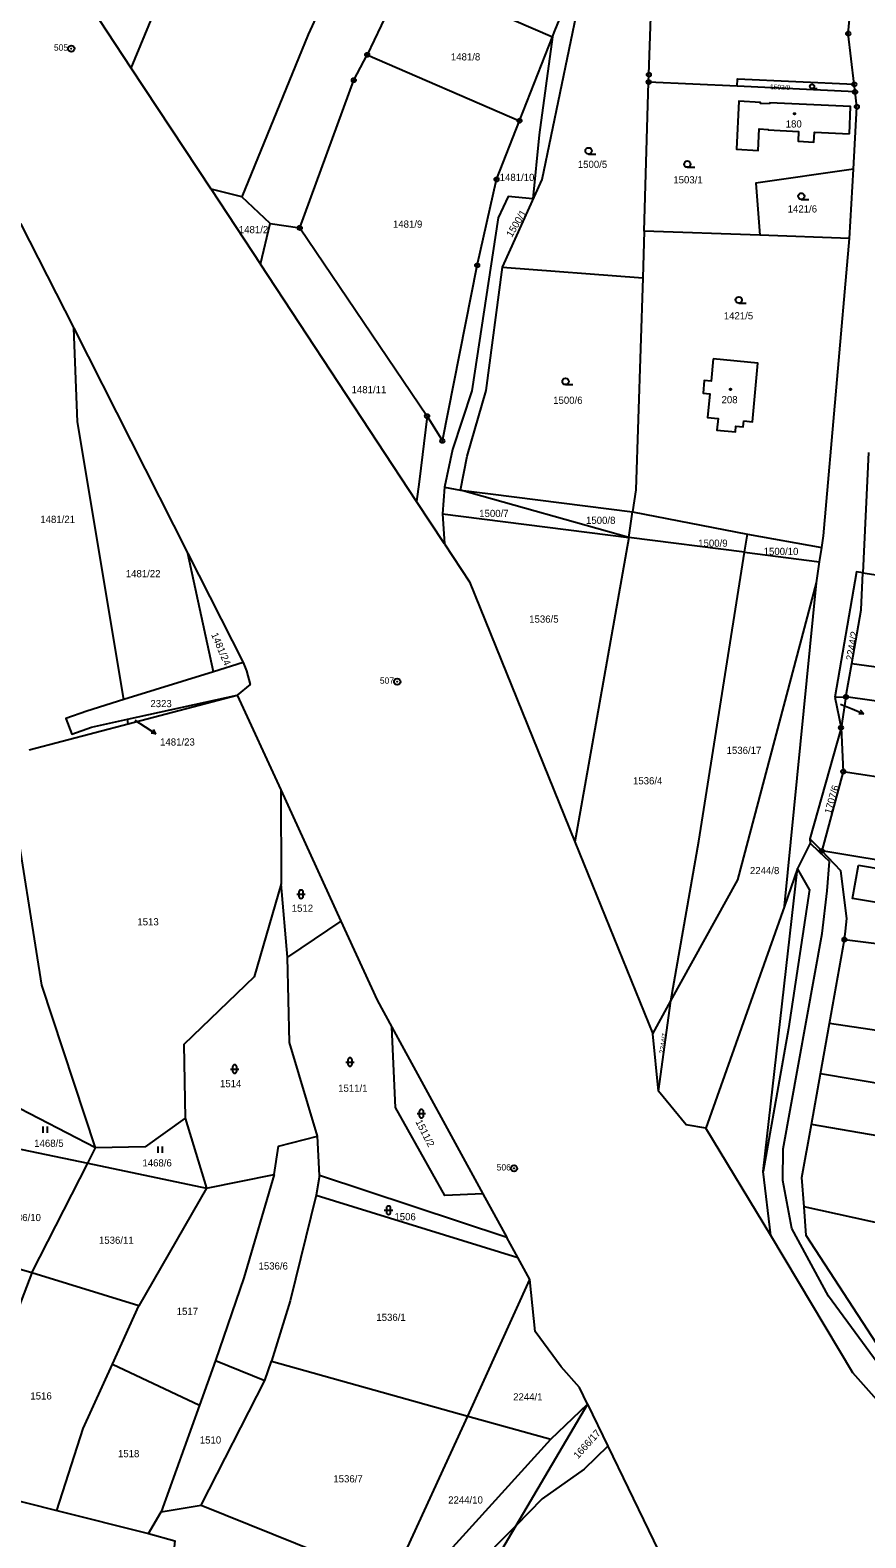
# Model space of a CAD drawing. Extents: x -725728 to -720881, y -1068679 to -1063504.
# Drawn here: x -723290.5 to -723092.7, y -1066402.9 to -1066046.1 of the extents above; entities that cross this region are included whole.
import ezdxf

# ---------------------------------------------------------------- set-up
doc = ezdxf.new("R2010")
doc.units = 0
for name, color, linetype in [('Hranice parcel', 7, 'Continuous'), ('Parcelní čísla', 7, 'Continuous'), ('Pop  PČ popisy', 7, 'Continuous'), ('Vnitřní kresba', 7, 'Continuous'), ('Značky bodu BP', 7, 'Continuous'), ('Značky budov', 7, 'Continuous'), ('Značky kultur', 7, 'Continuous')]:
    doc.layers.add(name, color=color, linetype=linetype)

# ---------------------------------------------------------------- blocks, each defined once
blk = doc.blocks.new('4.02_4')
at = {"layer": 'Značky budov'}
blk.add_circle((-0.001, 0), 0.0175, dxfattribs=at)
blk = doc.blocks.new('1029_117')
at = {"layer": 'Pop  PČ popisy'}
for p, q in [((0, 0), (0.276, -0.117)), ((0.276, -0.117), (0.164, -0.124)), ((0.276, -0.117), (0.204, -0.032))]:
    blk.add_line(p, q, dxfattribs=at)
blk = doc.blocks.new('1029_176')
at = {"layer": 'Pop  PČ popisy'}
for p, q in [((0, 0), (0.252, -0.163)), ((0.252, -0.163), (0.14, -0.151)), ((0.252, -0.163), (0.195, -0.067))]:
    blk.add_line(p, q, dxfattribs=at)
blk = doc.blocks.new('3.04_2')
at = {"layer": 'Značky kultur'}
blk.add_line((0.001, 0), (0.176, 0), dxfattribs=at)
blk.add_circle((0.001, 0.075), 0.075, dxfattribs=at)
blk = doc.blocks.new('3.16_3')
at = {"layer": 'Značky kultur'}
for p, q in [((-0.1, 0.1), (0.1, 0.1)), ((-0.05, 0.15), (-0.05, 0.05)), ((0.05, 0.05), (0.05, 0.15))]:
    blk.add_line(p, q, dxfattribs=at)
for centre, start, end in [((0, 0.15), 0, 180), ((0, 0.05), 180, 359.9879)]:
    blk.add_arc(centre, 0.05, start, end, dxfattribs=at)
blk = doc.blocks.new('3.16_2')
at = {"layer": 'Značky kultur'}
for p, q in [((-0.1, 0.1), (0.1, 0.1)), ((-0.05, 0.15), (-0.05, 0.05)), ((0.05, 0.05), (0.05, 0.15))]:
    blk.add_line(p, q, dxfattribs=at)
for centre, start, end in [((0, 0.15), 0, 180), ((0, 0.05), 180, 359.9879)]:
    blk.add_arc(centre, 0.05, start, end, dxfattribs=at)
blk = doc.blocks.new('3.04_4')
at = {"layer": 'Značky kultur'}
blk.add_line((0, 0), (0.118, 0), dxfattribs=at)
blk.add_circle((0, 0.05), 0.0502, dxfattribs=at)
blk = doc.blocks.new('3.06_1')
at = {"layer": 'Značky kultur'}
for p, q in [((-0.051, 0), (-0.051, 0.15)), ((0.049, 0), (0.049, 0.15))]:
    blk.add_line(p, q, dxfattribs=at)
blk = doc.blocks.new('1.01_1')
at = {"layer": 'Značky bodu BP'}
for radius in [0.075, 0.003]:
    blk.add_circle((0, 0), radius, dxfattribs=at)
blk = doc.blocks.new('1.05_1')
at = {"layer": 'Značky bodu BP'}
for radius in [0.05, 0.00303]:
    blk.add_circle((0, 0), radius, dxfattribs=at)
blk = doc.blocks.new('1.05_2')
at = {"layer": 'Značky bodu BP'}
for radius in [0.05, 0.00303]:
    blk.add_circle((0, 0), radius, dxfattribs=at)

msp = doc.modelspace()

# ---------------------------------------------------------------- linework, layer by layer
at = {"layer": 'Hranice parcel'}
for p, q in [((-723201.59, -1066032.7), (-723210.75, -1066051.97)), ((-723201.59, -1066032.7), (-723166.93, -1066047.71)), ((-723266.59, -1066055.14), (-723277.95, -1066037.89)), ((-723174.71, -1066067.58), (-723166.93, -1066047.71)), ((-723210.75, -1066051.97), (-723174.71, -1066067.58)), ((-723247.72, -1066083.8), (-723266.59, -1066055.14)), ((-723145.19, -1066093.7), (-723144.14, -1066058.44)), ((-723123.21, -1066059.43), (-723144.14, -1066058.44)), ((-723095.28, -1066060.75), (-723123.21, -1066059.43)), ((-723095.28, -1066060.75), (-723095.49, -1066058.96)), ((-723096.6, -1066095.41), (-723095.69, -1066079.02)), ((-723240.42, -1066085.57), (-723247.72, -1066083.8)), ((-723247.72, -1066083.8), (-723236.02, -1066101.56)), ((-723233.7, -1066091.89), (-723240.42, -1066085.57)), ((-723292.77, -1066091.87), (-723280.22, -1066116.65)), ((-723236.02, -1066101.56), (-723233.7, -1066091.89)), ((-723233.7, -1066091.89), (-723226.7, -1066092.94)), ((-723226.7, -1066092.94), (-723196.58, -1066137.49)), ((-723145.19, -1066093.7), (-723145.5, -1066104.76)), ((-723117.81, -1066094.66), (-723145.19, -1066093.7)), ((-723096.6, -1066095.41), (-723117.81, -1066094.66)), ((-723199.05, -1066157.71), (-723236.02, -1066101.56)), ((-723178.74, -1066102.26), (-723145.5, -1066104.76)), ((-723280.22, -1066116.65), (-723253.2, -1066169.99)), ((-723092.09, -1066146.13), (-723093.43, -1066174.58)), ((-723192.46, -1066154.33), (-723192.93, -1066160.62)), ((-723192.46, -1066154.33), (-723188.68, -1066154.97)), ((-723148.86, -1066166.23), (-723188.68, -1066154.97)), ((-723192.47, -1066167.7), (-723199.05, -1066157.71)), ((-723192.93, -1066160.62), (-723192.47, -1066167.7)), ((-723192.93, -1066160.62), (-723148.86, -1066166.23)), ((-723148.86, -1066166.23), (-723147.95, -1066160.12)), ((-723147.95, -1066160.12), (-723120.77, -1066165.42)), ((-723148.86, -1066166.23), (-723161.61, -1066238.2)), ((-723121.45, -1066169.69), (-723148.86, -1066166.23)), ((-723121.45, -1066169.69), (-723120.77, -1066165.42)), ((-723120.77, -1066165.42), (-723103.18, -1066168.56)), ((-723247.14, -1066198), (-723253.2, -1066169.99)), ((-723253.2, -1066169.99), (-723240.11, -1066195.82)), ((-723121.45, -1066169.69), (-723103.67, -1066171.93)), ((-723103.67, -1066171.93), (-723103.18, -1066168.56)), ((-723104.39, -1066176.91), (-723103.67, -1066171.93)), ((-723112.03, -1066253.46), (-723104.39, -1066176.91)), ((-723093.43, -1066174.58), (-723046.15, -1066181.81)), ((-723247.14, -1066198), (-723268.33, -1066204.57)), ((-723240.11, -1066195.82), (-723247.14, -1066198)), ((-723097.44, -1066203.92), (-723096.06, -1066196.04)), ((-723267.52, -1066209.22), (-723241.49, -1066203.53)), ((-723267.33, -1066210.31), (-723241.49, -1066203.53)), ((-723241.49, -1066203.53), (-723231.23, -1066225.92)), ((-723100.11, -1066204.03), (-723097.44, -1066203.92)), ((-723100.11, -1066204.03), (-723098.61, -1066211.22)), ((-723097.44, -1066203.92), (-723098.61, -1066211.22)), ((-723054.68, -1066209.91), (-723097.44, -1066203.92)), ((-723267.33, -1066210.31), (-723267.52, -1066209.22)), ((-723290.75, -1066216.46), (-723267.33, -1066210.31)), ((-723098.61, -1066211.22), (-723105.96, -1066237.53)), ((-723098.61, -1066211.22), (-723098.1, -1066221.59)), ((-723098.1, -1066221.59), (-723103.18, -1066240.39)), ((-723098.1, -1066221.59), (-723040.46, -1066230.47)), ((-723231.23, -1066225.92), (-723231.09, -1066248.16)), ((-723231.23, -1066225.92), (-723217, -1066256.99)), ((-723161.61, -1066238.2), (-723143.18, -1066283.69)), ((-723103.18, -1066240.39), (-723105.96, -1066237.53)), ((-723229.65, -1066265.5), (-723231.09, -1066248.16)), ((-723112.03, -1066253.46), (-723130.58, -1066306)), ((-723217, -1066256.99), (-723229.65, -1066265.5)), ((-723097.8, -1066261.37), (-723097.55, -1066259.39)), ((-723101.36, -1066281.23), (-723097.8, -1066261.37)), ((-723143.18, -1066283.69), (-723138.87, -1066275.9)), ((-723141.8, -1066297.25), (-723138.87, -1066275.9)), ((-723204.93, -1066282.09), (-723183.36, -1066321.5)), ((-723141.8, -1066297.25), (-723143.18, -1066283.69)), ((-723103.49, -1066293.15), (-723101.36, -1066281.23)), ((-723105.64, -1066305.13), (-723103.49, -1066293.15)), ((-723275.08, -1066310.68), (-723295.14, -1066300.27)), ((-723253.82, -1066303.65), (-723248.79, -1066320.21)), ((-723298.56, -1066309.75), (-723276.9, -1066314.3)), ((-723222.03, -1066317.17), (-723222.55, -1066307.92)), ((-723276.9, -1066314.3), (-723275.08, -1066310.68)), ((-723290.16, -1066340.27), (-723276.9, -1066314.3)), ((-723276.9, -1066314.3), (-723248.79, -1066320.21)), ((-723248.79, -1066320.21), (-723264.8, -1066348.08)), ((-723248.79, -1066320.21), (-723232.79, -1066316.99)), ((-723222.03, -1066317.17), (-723222.84, -1066321.87)), ((-723177.7, -1066331.85), (-723222.03, -1066317.17)), ((-723222.84, -1066321.87), (-723175.11, -1066336.58)), ((-723183.36, -1066321.5), (-723177.7, -1066331.85)), ((-723175.11, -1066336.58), (-723177.7, -1066331.85)), ((-723290.16, -1066340.27), (-723307.71, -1066335.16)), ((-723172.24, -1066341.83), (-723175.11, -1066336.58)), ((-723290.16, -1066340.27), (-723309.18, -1066390.15)), ((-723264.8, -1066348.08), (-723290.16, -1066340.27)), ((-723186.9, -1066374.14), (-723172.24, -1066341.83)), ((-723271.05, -1066361.86), (-723264.8, -1066348.08)), ((-723271.05, -1066361.86), (-723250.48, -1066371.55)), ((-723246.68, -1066360.96), (-723250.48, -1066371.55)), ((-723246.68, -1066360.96), (-723234.96, -1066365.75)), ((-723234.96, -1066365.75), (-723233.37, -1066361.13)), ((-723233.37, -1066361.13), (-723186.9, -1066374.14)), ((-723250.03, -1066395.24), (-723234.96, -1066365.75)), ((-723250.48, -1066371.55), (-723259.55, -1066396.81)), ((-723158.61, -1066371.29), (-723175.61, -1066400.08)), ((-723167.33, -1066379.61), (-723158.61, -1066371.29)), ((-723158.61, -1066371.29), (-723153.78, -1066381.27)), ((-723204.98, -1066413.32), (-723186.9, -1066374.14)), ((-723186.9, -1066374.14), (-723167.33, -1066379.61)), ((-723199.76, -1066415.34), (-723167.33, -1066379.61)), ((-723153.78, -1066381.27), (-723129.59, -1066431.22)), ((-723309.18, -1066390.15), (-723284.22, -1066396.46)), ((-723259.55, -1066396.81), (-723250.03, -1066395.24)), ((-723250.03, -1066395.24), (-723204.98, -1066413.32)), ((-723284.22, -1066396.46), (-723262.52, -1066401.95)), ((-723262.52, -1066401.95), (-723259.55, -1066396.81)), ((-723175.61, -1066400.08), (-723185.78, -1066410.37)), ((-723175.61, -1066400.08), (-723182.48, -1066411.72))]:
    msp.add_line(p, q, dxfattribs=at)
for points in [[(-723266.59, -1066055.14), (-723248.19, -1066010.49), (-723236.89, -1065987.18), (-723199.64, -1065923.34)], [(-723184.28, -1065968.06), (-723206.5, -1066007.47), (-723224.7, -1066047.21), (-723240.42, -1066085.57)], [(-723178.74, -1066102.26), (-723169.36, -1066081.47), (-723160.79, -1066040.44)], [(-723166.93, -1066047.71), (-723166.37, -1066046.27), (-723163.77, -1066040)], [(-723095.49, -1066058.96), (-723096.9, -1066046.94), (-723096.47, -1066042), (-723096.32, -1066039.95)], [(-723144.14, -1066058.44), (-723144.09, -1066056.67), (-723143.66, -1066042.96)], [(-723166.93, -1066047.71), (-723170.08, -1066070.91), (-723171.59, -1066086.1), (-723177.43, -1066085.54), (-723179.77, -1066090.58), (-723185.97, -1066131.47), (-723190.53, -1066145.38), (-723192.46, -1066154.33)], [(-723226.7, -1066092.94), (-723213.92, -1066057.98), (-723210.75, -1066051.97)], [(-723123.21, -1066059.43), (-723123.13, -1066057.66), (-723095.49, -1066058.96)], [(-723115.51, -1066063.59), (-723117.68, -1066063.49), (-723117.67, -1066063.23), (-723122.8, -1066062.97), (-723123.36, -1066074.34), (-723118.25, -1066074.59), (-723117.99, -1066069.52), (-723115.83, -1066069.63), (-723115.84, -1066069.77), (-723108.66, -1066070.12), (-723108.77, -1066072.43), (-723105.01, -1066072.62), (-723104.89, -1066070.3), (-723096.62, -1066070.69)], [(-723096.62, -1066070.69), (-723096.36, -1066064.21), (-723115.48, -1066063.33), (-723115.51, -1066063.59)], [(-723095.69, -1066079.02), (-723094.87, -1066064.28), (-723095.28, -1066060.75)], [(-723196.58, -1066137.49), (-723192.97, -1066143.34), (-723184.72, -1066101.81), (-723180.15, -1066081.47), (-723174.71, -1066067.58)], [(-723095.69, -1066079.02), (-723118.75, -1066082.35), (-723117.81, -1066094.66)], [(-723103.18, -1066168.56), (-723102.78, -1066165.83), (-723096.6, -1066095.41)], [(-723188.68, -1066154.97), (-723187.11, -1066146.98), (-723182.59, -1066131.46), (-723178.74, -1066102.26)], [(-723145.5, -1066104.76), (-723147.17, -1066154.89), (-723147.95, -1066160.12)], [(-723268.33, -1066204.57), (-723279.35, -1066138.87), (-723280.22, -1066116.65)], [(-723128.89, -1066123.94), (-723129.38, -1066129.24), (-723131, -1066129.09), (-723131.28, -1066132.08), (-723129.66, -1066132.23), (-723130.18, -1066137.82), (-723127.71, -1066138.05), (-723127.97, -1066140.82), (-723123.62, -1066141.22), (-723123.49, -1066139.84), (-723121.76, -1066140), (-723121.63, -1066138.62)], [(-723121.63, -1066138.62), (-723119.56, -1066138.81), (-723118.27, -1066124.93), (-723128.89, -1066123.94)], [(-723196.58, -1066137.49), (-723198.48, -1066153.07), (-723199.05, -1066157.71)], [(-723188.68, -1066154.97), (-723181.6, -1066155.87), (-723147.95, -1066160.12)], [(-723192.47, -1066167.7), (-723186.53, -1066176.72), (-723161.61, -1066238.2)], [(-723138.87, -1066275.9), (-723132.3, -1066238.05), (-723121.45, -1066169.69)], [(-723138.87, -1066275.9), (-723123, -1066247.21), (-723104.39, -1066176.91)], [(-723093.43, -1066174.58), (-723094.98, -1066174.34), (-723100.11, -1066204.03)], [(-723096.06, -1066196.04), (-723093.84, -1066183.3), (-723093.43, -1066174.58)], [(-723096.06, -1066196.04), (-723049.31, -1066202.45), (-723046.15, -1066181.81)], [(-723240.11, -1066195.82), (-723239.34, -1066197.78), (-723238.48, -1066200.97), (-723241.49, -1066203.53)], [(-723268.33, -1066204.57), (-723277.12, -1066207.29), (-723282.04, -1066209.07), (-723280.67, -1066212.75), (-723276, -1066211.08), (-723267.52, -1066209.22)], [(-723275.08, -1066310.68), (-723287.72, -1066272.16), (-723294.76, -1066227.83)], [(-723105.96, -1066237.53), (-723105.95, -1066238.53), (-723108.89, -1066244.58), (-723112.03, -1066253.46)], [(-723097.55, -1066259.39), (-723097.24, -1066256.37), (-723098.63, -1066245.07), (-723103.18, -1066240.39)], [(-722921.42, -1066263.84), (-722997.15, -1066255.08), (-723038.53, -1066251.13), (-723103.18, -1066240.39)], [(-723094.51, -1066243.73), (-723082.34, -1066245.82), (-723083.66, -1066253.7), (-723095.88, -1066251.66), (-723094.51, -1066243.73)], [(-723231.09, -1066248.16), (-723237.53, -1066270.22), (-723254.16, -1066286.17), (-723253.82, -1066303.65)], [(-723217, -1066256.99), (-723208.43, -1066275.69), (-723204.93, -1066282.09)], [(-723097.8, -1066261.37), (-723033.39, -1066269.43), (-722991.65, -1066272.59), (-722923.76, -1066280.04)], [(-723222.55, -1066307.92), (-723229.14, -1066285.74), (-723229.65, -1066265.5)], [(-723183.36, -1066321.5), (-723192.39, -1066321.97), (-723204.02, -1066301.12), (-723204.93, -1066282.09)], [(-722924.25, -1066309.26), (-722959.48, -1066300.12), (-722980.67, -1066296.27), (-723004.51, -1066293.75), (-723038.81, -1066290.57), (-723101.36, -1066281.23)], [(-722926.1, -1066320.92), (-722966.23, -1066312.44), (-723038.3, -1066304.11), (-723103.49, -1066293.15)], [(-723130.58, -1066306), (-723135.29, -1066305.19), (-723141.8, -1066297.25)], [(-723253.82, -1066303.65), (-723263.32, -1066310.44), (-723275.08, -1066310.68)], [(-723012.96, -1066526.89), (-723018.76, -1066497.16), (-723026.55, -1066478.26), (-723053.67, -1066426.46), (-723067.28, -1066399.64), (-723068.8, -1066398.54), (-723078.09, -1066383.87), (-723095.78, -1066363.91), (-723105.55, -1066347.67), (-723115.24, -1066331.37), (-723130.58, -1066306)], [(-723107.37, -1066324.63), (-723107.89, -1066317.71), (-723105.64, -1066305.13)], [(-722928.35, -1066333.78), (-722969.27, -1066325.17), (-722991.14, -1066322.25), (-723029.15, -1066318.28), (-723105.64, -1066305.13)], [(-723232.79, -1066316.99), (-723231.73, -1066310.22), (-723222.55, -1066307.92)], [(-723232.79, -1066316.99), (-723239.98, -1066341.44), (-723246.68, -1066360.96)], [(-723222.84, -1066321.87), (-723228.98, -1066346.84), (-723233.37, -1066361.13)], [(-723089.02, -1066358.78), (-723106.86, -1066331.36), (-723107.37, -1066324.63)], [(-722933.38, -1066353), (-722974.97, -1066343.46), (-723042.65, -1066336.44), (-723071.13, -1066332.59), (-723107.37, -1066324.63)], [(-723158.61, -1066371.29), (-723160.51, -1066367.37), (-723164.82, -1066362.44), (-723170.98, -1066354.11), (-723172.24, -1066341.83)], [(-723284.22, -1066396.46), (-723277.97, -1066377.11), (-723271.05, -1066361.86)], [(-723153.78, -1066381.27), (-723159.41, -1066386.67), (-723169.34, -1066393.74), (-723175.61, -1066400.08)], [(-723262.52, -1066401.95), (-723256.26, -1066403.65), (-723259.55, -1066434.36)]]:
    msp.add_lwpolyline(points, dxfattribs=at)
at = {"layer": 'Pop  PČ popisy'}
for p, q in [((-723098.7, -1066205.63), (-723096.01, -1066206.78)), ((-723265.77, -1066209.43), (-723263.3, -1066211.01))]:
    msp.add_line(p, q, dxfattribs=at)
at = {"layer": 'Vnitřní kresba'}
for p, q in [((-723103.73, -1066240.64), (-723105.95, -1066238.53)), ((-723101.35, -1066242.89), (-723103.73, -1066240.64)), ((-723117.04, -1066316.28), (-723108.89, -1066244.58)), ((-723106.1, -1066249.48), (-723108.89, -1066244.58)), ((-723101.87, -1066249.86), (-723101.35, -1066242.89)), ((-723106.1, -1066249.48), (-723111.06, -1066282.37)), ((-723103.07, -1066259.89), (-723101.87, -1066249.86)), ((-723112.34, -1066310.86), (-723103.07, -1066259.89)), ((-723111.06, -1066282.37), (-723117.04, -1066316.28)), ((-723112.42, -1066318.35), (-723112.34, -1066310.86)), ((-723115.24, -1066331.37), (-723117.04, -1066316.28)), ((-723110.27, -1066329.75), (-723112.42, -1066318.35)), ((-723101.6, -1066345.75), (-723110.27, -1066329.75)), ((-723074.58, -1066382.67), (-723101.6, -1066345.75))]:
    msp.add_line(p, q, dxfattribs=at)

# ---------------------------------------------------------------- block references
at = {"layer": 'Pop  PČ popisy', "xscale": 10, "yscale": 10}
for name, p in [('1029_117', (-723096.01, -1066206.78)), ('1029_176', (-723263.3, -1066211.01))]:
    msp.add_blockref(name, p, dxfattribs=at)
at = {"layer": 'Značky bodu BP', "xscale": 10, "yscale": 10}
for name, p in [('1.05_1', (-723096.9, -1066046.94)), ('1.01_1', (-723280.8, -1066050.51)), ('1.05_1', (-723210.75, -1066051.97)), ('1.05_2', (-723144.09, -1066056.67)), ('1.05_1', (-723213.92, -1066057.98)), ('1.05_1', (-723144.14, -1066058.44)), ('1.05_1', (-723095.49, -1066058.96)), ('1.05_1', (-723095.28, -1066060.75)), ('1.05_1', (-723174.71, -1066067.58)), ('1.05_1', (-723094.87, -1066064.28)), ('1.05_1', (-723180.15, -1066081.47)), ('1.05_1', (-723226.7, -1066092.94)), ('1.05_1', (-723184.72, -1066101.81)), ('1.05_1', (-723196.58, -1066137.49)), ('1.05_1', (-723192.97, -1066143.34)), ('1.01_1', (-723203.66, -1066200.33)), ('1.05_2', (-723097.44, -1066203.92)), ('1.05_1', (-723098.61, -1066211.22)), ('1.05_1', (-723098.1, -1066221.59)), ('1.05_2', (-723103.18, -1066240.39)), ('1.05_1', (-723097.8, -1066261.37)), ('1.01_1', (-723176, -1066315.51))]:
    msp.add_blockref(name, p, dxfattribs=at)
at = {"layer": 'Značky budov', "xscale": 10, "yscale": 10}
for p in [(-723109.61, -1066065.93), (-723124.76, -1066131.14)]:
    msp.add_blockref('4.02_4', p, dxfattribs=at)
at = {"layer": 'Značky kultur', "xscale": 10, "yscale": 10}
for name, p in [('3.04_4', (-723105.47, -1066059.95)), ('3.04_2', (-723158.37, -1066075.46)), ('3.04_2', (-723135, -1066078.59)), ('3.04_2', (-723108.03, -1066086.2)), ('3.04_2', (-723122.82, -1066110.74)), ('3.04_2', (-723163.83, -1066130.04)), ('3.16_3', (-723226.4, -1066251.64)), ('3.16_2', (-723242.12, -1066293)), ('3.16_2', (-723214.83, -1066291.35)), ('3.16_2', (-723197.92, -1066303.56)), ('3.06_1', (-723286.9, -1066307.11)), ('3.06_1', (-723259.69, -1066311.82)), ('3.16_3', (-723205.71, -1066326.42))]:
    msp.add_blockref(name, p, dxfattribs=at)

# ---------------------------------------------------------------- texts
at = {"layer": 'Parcelní čísla'}
for s, p in [('1481/8', (-723190.95, -1066053.31)), ('180', (-723111.7, -1066069.18)), ('1500/5', (-723160.91, -1066078.75)), ('1481/10', (-723179.4, -1066081.83)), ('1503/1', (-723138.31, -1066082.41)), ('1421/6', (-723111.24, -1066089.3)), ('1481/9', (-723204.66, -1066092.89)), ('1481/2', (-723241.13, -1066094.19)), ('1421/5', (-723126.36, -1066114.59)), ('1481/11', (-723214.45, -1066132.07)), ('1500/6', (-723166.74, -1066134.58)), ('208', (-723126.89, -1066134.44)), ('1500/7', (-723184.24, -1066161.36)), ('1481/21', (-723288.12, -1066162.77)), ('1500/8', (-723158.96, -1066162.99)), ('1500/9', (-723132.41, -1066168.4)), ('1500/10', (-723116.92, -1066170.35)), ('1481/22', (-723267.89, -1066175.61)), ('1536/5', (-723172.41, -1066186.36)), ('2323', (-723262.07, -1066206.36)), ('1481/23', (-723259.77, -1066215.45)), ('1536/17', (-723125.69, -1066217.43)), ('1536/4', (-723147.85, -1066224.63)), ('2244/8', (-723120.17, -1066245.87)), ('1512', (-723228.61, -1066254.79)), ('1513', (-723265.15, -1066258)), ('1514', (-723245.6, -1066296.3)), ('1511/1', (-723217.62, -1066297.38)), ('1468/5', (-723289.56, -1066310.42)), ('1468/6', (-723263.95, -1066315.06)), ('1536/10', (-723296.19, -1066327.99)), ('1506', (-723204.31, -1066327.8)), ('1536/11', (-723274.24, -1066333.36)), ('1536/6', (-723236.47, -1066339.46)), ('1517', (-723255.84, -1066350.2)), ('1536/1', (-723208.59, -1066351.61)), ('1516', (-723290.47, -1066370.21)), ('2244/1', (-723176.21, -1066370.44)), ('1510', (-723250.37, -1066380.64)), ('1518', (-723269.74, -1066383.87)), ('1536/7', (-723218.77, -1066389.83)), ('2244/10', (-723191.59, -1066394.83))]:
    msp.add_text(s, height=1.7, dxfattribs=at).set_placement(p)
for s, height, rotation, p in [('1503/9', 1.139, 357, (-723115.47, -1066060.09)), ('1500/1', 1.7, 59, (-723176.52, -1066095.3)), ('1481/24', 1.7, 293, (-723247.73, -1066189.15)), ('2244/2', 1.7, 80, (-723095.8, -1066195.44)), ('1707/6', 1.7, 74, (-723100.96, -1066231.77)), ('2244/7', 1.14, 81, (-723140.53, -1066288.41)), ('1511/2', 1.7, 297, (-723199.39, -1066304.46)), ('1666/17', 1.7, 48, (-723160.86, -1066384.38))]:
    msp.add_text(s, height=height, rotation=rotation, dxfattribs=at).set_placement(p)
at = {"layer": 'Značky bodu BP'}
for s, p in [('505', (-723284.9, -1066051.01)), ('507', (-723207.75, -1066200.83)), ('506', (-723180.1, -1066316.01))]:
    msp.add_text(s, height=1.5, dxfattribs=at).set_placement(p)

doc.saveas('drawing.dxf')
